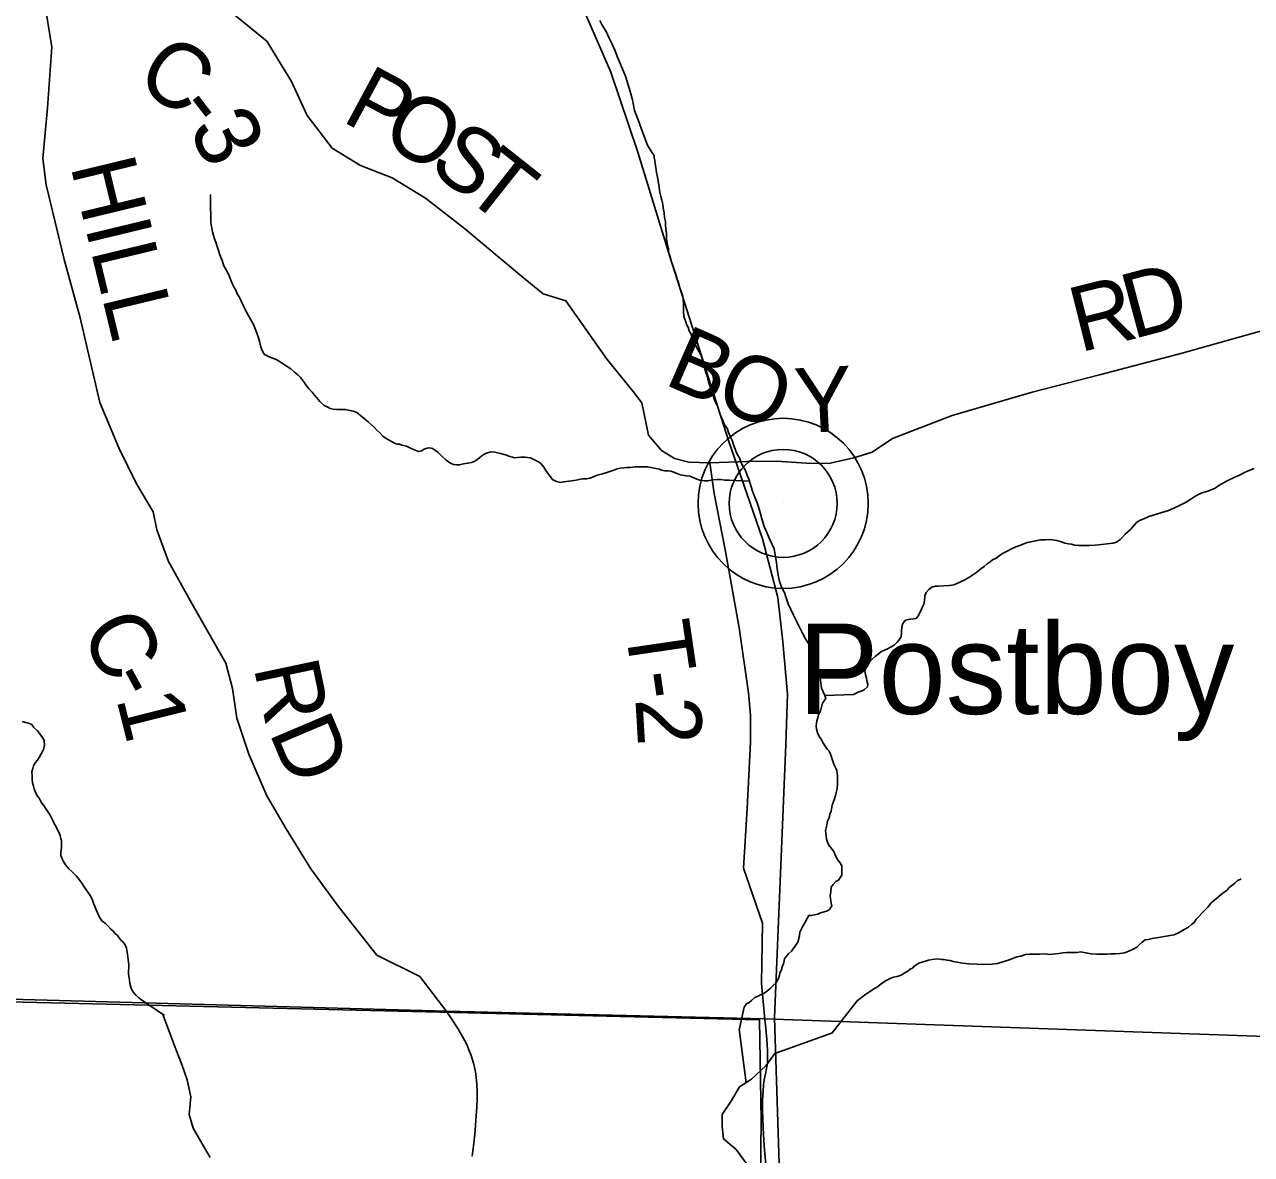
# Model space of a CAD drawing. Extents: x -14196 to 143, y -6096 to 28.
# Drawn here: x 58.549 to 59.622, y 18.723 to 19.711 of the extents above; entities that cross this region are included whole.
import ezdxf

# ---------------------------------------------------------------- set-up
doc = ezdxf.new("R2010")
doc.units = 0
for name, color, linetype in [('GM_X_Corporation', 7, 'Continuous'), ('GM_X_County_Road', 7, 'Continuous'), ('GM_X_County_Road_Text', 7, 'Continuous'), ('GM_X_Minor_River', 7, 'Continuous'), ('GM_X_Rail_Line', 7, 'Continuous'), ('GM_X_Township_Road', 7, 'Continuous'), ('GM_X_Township_Road_Text', 7, 'Continuous'), ('GM_X_Unincorporated', 7, 'Continuous'), ('GM_X_Unincorporated_Location', 7, 'Continuous'), ('GM_X_Unincorporated_Text', 7, 'Continuous')]:
    doc.layers.add(name, color=color, linetype=linetype)

msp = doc.modelspace()

# ---------------------------------------------------------------- linework, layer by layer
at = {"layer": 'GM_X_Corporation'}
for points in [[(58.1028, 23.6985), (58.1028, 18.8711), (58.9182, 18.8487), (59.1965, 18.8421), (59.6927, 18.8245), (59.855, 18.8221), (59.8722, 18.8218), (60.8954, 18.8061)], [(58.1028, 23.6985), (58.1028, 18.8711), (58.9182, 18.8487), (59.1965, 18.8421), (59.6927, 18.8245), (59.855, 18.8221), (59.8722, 18.8218), (60.8954, 18.8061)], [(60.8954, 18.8061), (59.8722, 18.8218), (59.855, 18.8221), (59.6927, 18.8245), (59.1965, 18.8421), (58.9182, 18.8487), (58.1028, 18.8711), (58.1028, 16.8985), (64.9028, 16.8985)], [(60.8954, 18.8061), (59.8722, 18.8218), (59.855, 18.8221), (59.6927, 18.8245), (59.1965, 18.8421), (58.9182, 18.8487), (58.1028, 18.8711), (58.1028, 16.8985), (62.3117, 16.8985)]]:
    msp.add_lwpolyline(points, dxfattribs=at)
msp.add_lwpolyline([(59.1921, 18.8411), (59.1934, 18.7532), (59.1927, 18.677), (59.1861, 17.9645), (58.1763, 17.99), (58.1952, 18.865)], close=True, dxfattribs=at)
at = {"layer": 'GM_X_County_Road'}
for points in [[(58.9184, 18.8482), (58.8948, 18.879), (58.8574, 18.8977), (58.8236, 18.9405), (58.7996, 18.9733), (58.7779, 19.0081), (58.7612, 19.037), (58.7454, 19.0734), (58.7348, 19.1051), (58.7311, 19.1308), (58.7252, 19.1531), (58.6954, 19.2052), (58.6751, 19.2419), (58.6649, 19.2698), (58.6618, 19.2853), (58.6468, 19.3104), (58.6316, 19.3415), (58.615, 19.381), (58.5979, 19.4551), (58.5837, 19.5061), (58.568, 19.5714), (58.5651, 19.5945), (58.5693, 19.6387), (58.5729, 19.6917), (58.5662, 19.7333)], [(58.7251, 19.726), (58.7612, 19.6969), (58.7826, 19.6617), (58.7963, 19.632), (58.8183, 19.6033), (58.8429, 19.5883), (58.8706, 19.5776), (58.8999, 19.5598), (58.934, 19.5333), (58.9856, 19.4901), (59.0027, 19.4761), (59.0226, 19.4698), (59.0588, 19.4186), (59.0815, 19.3907), (59.089, 19.3806), (59.095, 19.3523), (59.1064, 19.3389), (59.1176, 19.3319), (59.1302, 19.3288), (59.1484, 19.3282), (59.1815, 19.3294), (59.2069, 19.3297), (59.2332, 19.3281), (59.2525, 19.3278), (59.2744, 19.3325), (59.2906, 19.3375), (59.3082, 19.3494), (59.3605, 19.3697), (59.4306, 19.3901), (59.4895, 19.4053), (59.5604, 19.4238), (59.6011, 19.4351), (59.6362, 19.4451)], [(58.9406, 18.7221), (58.9416, 18.7288), (58.942, 18.733), (58.9427, 18.7385), (58.9432, 18.7447), (58.9443, 18.7576), (58.9448, 18.765), (58.9451, 18.7718), (58.945, 18.7786), (58.9448, 18.7847), (58.9446, 18.7878), (58.9442, 18.7908), (58.9438, 18.7939), (58.9433, 18.7968), (58.9426, 18.7999), (58.9417, 18.8034), (58.9398, 18.8099), (58.9379, 18.815), (58.936, 18.8195), (58.9326, 18.826), (58.9281, 18.8335), (58.9231, 18.8412), (58.9184, 18.8482)]]:
    msp.add_lwpolyline(points, dxfattribs=at)
at = {"layer": 'GM_X_Minor_River'}
for points in [[(59.0522, 19.7151), (59.0545, 19.7109), (59.058, 19.7053), (59.0604, 19.6996), (59.0631, 19.6943), (59.0654, 19.689), (59.0678, 19.6829), (59.0705, 19.6769), (59.0725, 19.672), (59.0748, 19.6663), (59.0768, 19.6598), (59.0788, 19.653)], [(59.0788, 19.653), (59.0808, 19.6458), (59.0828, 19.6364), (59.0863, 19.6273), (59.0898, 19.6167), (59.0941, 19.6061), (59.098, 19.5993), (59.1, 19.597), (59.1, 19.5951), (59.1004, 19.5925), (59.1008, 19.5898), (59.1012, 19.5864), (59.102, 19.5822), (59.1028, 19.578), (59.1037, 19.5731), (59.1041, 19.5689), (59.1049, 19.5648), (59.1057, 19.561), (59.1065, 19.5579), (59.1073, 19.5545), (59.1077, 19.5511), (59.1085, 19.5469), (59.109, 19.5428), (59.1098, 19.5393), (59.1098, 19.5363), (59.1102, 19.5325), (59.1106, 19.5287), (59.1107, 19.5242), (59.1111, 19.5204), (59.1119, 19.5173), (59.1123, 19.5154), (59.1124, 19.5124), (59.1135, 19.5094), (59.1143, 19.5063), (59.1151, 19.5037), (59.1163, 19.5007), (59.1183, 19.4946), (59.1191, 19.4923), (59.1199, 19.4889), (59.1214, 19.4851), (59.1222, 19.4813), (59.1238, 19.4772), (59.125, 19.4738), (59.1254, 19.4673), (59.1255, 19.4605), (59.1259, 19.4563), (59.1267, 19.454), (59.1275, 19.4514), (59.1283, 19.4487), (59.1295, 19.4468), (59.1306, 19.4438), (59.1318, 19.4412), (59.133, 19.4385), (59.1346, 19.4351), (59.1357, 19.4321), (59.1369, 19.4294), (59.1392, 19.4253), (59.1412, 19.4211), (59.1424, 19.4173), (59.1436, 19.4124), (59.1448, 19.4079), (59.1459, 19.4052), (59.1467, 19.4014), (59.1479, 19.3972), (59.1495, 19.3938), (59.1507, 19.3897), (59.1526, 19.3832), (59.1542, 19.3802), (59.1554, 19.3776), (59.1562, 19.3753), (59.157, 19.3723), (59.1581, 19.3692), (59.1593, 19.3666), (59.1605, 19.3636), (59.162, 19.3605), (59.1636, 19.3586), (59.1648, 19.3549), (59.1663, 19.3515), (59.1671, 19.3496), (59.1683, 19.3473), (59.1695, 19.3431), (59.1706, 19.3401), (59.1718, 19.3371), (59.1734, 19.3344), (59.1745, 19.3325), (59.1757, 19.3288), (59.1776, 19.325), (59.1796, 19.3216), (59.1812, 19.3174), (59.1827, 19.314), (59.1839, 19.3102), (59.1859, 19.3034), (59.1878, 19.2981), (59.1898, 19.2932), (59.191, 19.2898), (59.1926, 19.2849), (59.1941, 19.2792), (59.1961, 19.2727), (59.1985, 19.2674), (59.2008, 19.2618), (59.2032, 19.2568)], [(58.7118, 19.5628), (58.7118, 19.5625), (58.7119, 19.5575), (58.7119, 19.5533), (58.7119, 19.5503), (58.712, 19.5461), (58.712, 19.5427), (58.7121, 19.5389), (58.7125, 19.5362), (58.7129, 19.5336), (58.7137, 19.5302), (58.7145, 19.5271), (58.7153, 19.5241), (58.7165, 19.5211), (58.7176, 19.5173), (58.7188, 19.5139), (58.72, 19.5101), (58.722, 19.5052), (58.7235, 19.5006), (58.7259, 19.4965), (58.7278, 19.4927), (58.7294, 19.4889), (58.7309, 19.4851), (58.7325, 19.4817), (58.7341, 19.4791), (58.7352, 19.4761), (58.7368, 19.4734), (58.7383, 19.4704), (58.7403, 19.4659), (58.7426, 19.4613), (58.7446, 19.4579), (58.7496, 19.4485), (58.7508, 19.4454), (58.752, 19.4424), (58.7535, 19.4383), (58.7547, 19.4345), (58.7555, 19.4307), (58.7563, 19.428), (58.7575, 19.4254), (58.759, 19.4231), (58.7621, 19.4216), (58.7651, 19.4201), (58.7686, 19.419), (58.7713, 19.4175), (58.7739, 19.4157), (58.7781, 19.4131), (58.782, 19.4104), (58.7854, 19.4074), (58.7881, 19.4052), (58.7904, 19.4029), (58.7927, 19.4003), (58.7947, 19.3973), (58.7978, 19.3931), (58.8008, 19.3901), (58.8031, 19.3871), (58.8074, 19.3818), (58.8112, 19.3784), (58.8143, 19.377), (58.8166, 19.3758), (58.8192, 19.3751), (58.8223, 19.3748), (58.8261, 19.3748), (58.8299, 19.3748), (58.8337, 19.3741), (58.8367, 19.3734), (58.8398, 19.3723), (58.8429, 19.3697), (58.8463, 19.367), (58.8498, 19.364), (58.8524, 19.3618), (58.8551, 19.3595), (58.8574, 19.3569), (58.8601, 19.3543), (58.8624, 19.3516), (58.8655, 19.3494), (58.8732, 19.3453), (58.8751, 19.3445), (58.877, 19.3446), (58.8793, 19.3438), (58.8831, 19.3427), (58.8873, 19.3409), (58.8907, 19.3394), (58.8938, 19.3383), (58.8964, 19.3387), (58.8987, 19.3402), (58.9013, 19.341), (58.9036, 19.3414), (58.9059, 19.3407), (58.9078, 19.3396), (58.9109, 19.3373), (58.9139, 19.3343), (58.9178, 19.3306), (58.9216, 19.3279), (58.9243, 19.3268), (58.9269, 19.3265), (58.9296, 19.3265), (58.933, 19.3273), (58.9368, 19.3281), (58.9402, 19.3285), (58.9429, 19.3297), (58.9455, 19.3316)], [(58.9455, 19.3316), (58.9493, 19.3347), (58.953, 19.3366), (58.9572, 19.3378), (58.9606, 19.3375), (58.9656, 19.3364), (58.9698, 19.3353), (58.9736, 19.3338), (58.9759, 19.3331), (58.9778, 19.3327), (58.9804, 19.3328), (58.9831, 19.3332), (58.9869, 19.3332), (58.9892, 19.3328), (58.9918, 19.3325), (58.9987, 19.3291), (59.0006, 19.3276), (59.0033, 19.3246), (59.0052, 19.3216), (59.008, 19.3175), (59.011, 19.3137), (59.0145, 19.3118), (59.0179, 19.3111), (59.0209, 19.3115), (59.0255, 19.3123), (59.0316, 19.3132), (59.0369, 19.3144), (59.0407, 19.3144), (59.0437, 19.3148), (59.0467, 19.316), (59.0501, 19.3175), (59.0547, 19.3187), (59.0577, 19.3195), (59.0611, 19.3207), (59.0645, 19.3219), (59.0675, 19.323), (59.0702, 19.3235), (59.0732, 19.3239), (59.0759, 19.3243), (59.0793, 19.3243), (59.0831, 19.3247), (59.0873, 19.3248), (59.0903, 19.3248), (59.0941, 19.3248), (59.0971, 19.3241), (59.1013, 19.3234), (59.1044, 19.3227), (59.1063, 19.3219), (59.1093, 19.3212), (59.112, 19.3212), (59.1143, 19.3209), (59.1162, 19.3205), (59.123, 19.3179), (59.128, 19.3168), (59.131, 19.3165), (59.1345, 19.315), (59.1371, 19.3139), (59.1406, 19.3128), (59.144, 19.3125), (59.147, 19.3125), (59.1508, 19.3133), (59.155, 19.3137), (59.158, 19.3137), (59.1618, 19.313), (59.1637, 19.313), (59.1656, 19.3131), (59.1832, 19.3123)], [(59.5545, 19.2887), (59.5594, 19.291), (59.5647, 19.2937), (59.5692, 19.2965), (59.5737, 19.2995), (59.579, 19.3019), (59.5832, 19.3031), (59.587, 19.3046), (59.5904, 19.3062), (59.5938, 19.3085), (59.5979, 19.3108), (59.6021, 19.3131), (59.607, 19.3155), (59.6119, 19.3174), (59.6157, 19.3194), (59.6194, 19.3213), (59.6247, 19.3233)], [(59.2492, 19.1247), (59.2742, 19.1257), (59.2784, 19.1277), (59.2818, 19.1289), (59.2837, 19.13), (59.2863, 19.1323), (59.2867, 19.1346), (59.2859, 19.1376), (59.2855, 19.1399), (59.2847, 19.143), (59.2842, 19.1464), (59.2853, 19.1498), (59.2868, 19.1517), (59.2883, 19.154), (59.2906, 19.1567), (59.2932, 19.159), (59.2988, 19.1632), (59.3038, 19.1656), (59.3072, 19.1675), (59.3098, 19.1687), (59.3124, 19.1714), (59.3139, 19.1733), (59.3158, 19.176), (59.3161, 19.1798), (59.3161, 19.1817), (59.3165, 19.1836), (59.3168, 19.1862), (59.3179, 19.1885), (59.3198, 19.1908), (59.3221, 19.1912), (59.3243, 19.1916), (59.327, 19.1917), (59.3289, 19.1921), (59.3311, 19.1947), (59.3322, 19.1974), (59.3334, 19.1993), (59.3341, 19.2012), (59.3356, 19.2047), (59.3363, 19.2077), (59.3366, 19.2119), (59.3377, 19.215), (59.34, 19.2176), (59.3426, 19.2196), (59.3456, 19.2204), (59.3483, 19.2204), (59.3578, 19.2209), (59.3601, 19.2213), (59.362, 19.2217), (59.3639, 19.2225), (59.3673, 19.224), (59.371, 19.2256), (59.3756, 19.2283), (59.3786, 19.2302), (59.3812, 19.2321), (59.3835, 19.2337), (59.3857, 19.2356), (59.3884, 19.2375), (59.391, 19.2398), (59.3936, 19.2418), (59.3959, 19.2433), (59.3989, 19.2449), (59.4015, 19.2468), (59.4046, 19.2491), (59.4091, 19.2514), (59.4129, 19.2534), (59.4163, 19.2549), (59.4197, 19.2561), (59.4231, 19.2573), (59.4261, 19.2585), (59.4295, 19.2593), (59.4333, 19.2601), (59.4378, 19.2609), (59.442, 19.2609), (59.4466, 19.2613), (59.4519, 19.2603), (59.4561, 19.2592), (59.4591, 19.258), (59.4622, 19.2573), (59.4649, 19.257), (59.4679, 19.2562), (59.4713, 19.2559), (59.4755, 19.2559), (59.4804, 19.256), (59.4857, 19.2564), (59.4911, 19.2569), (59.496, 19.2573), (59.5013, 19.2581), (59.5043, 19.2589), (59.5073, 19.2612), (59.5092, 19.2631), (59.5118, 19.2658), (59.5141, 19.2678), (59.5164, 19.2701), (59.5216, 19.2762), (59.5242, 19.2777), (59.528, 19.2793), (59.5325, 19.2812), (59.5382, 19.2832), (59.5439, 19.2848), (59.5496, 19.2867), (59.5545, 19.2887)], [(59.2032, 19.2568), (59.2047, 19.2531), (59.2063, 19.2443), (59.2068, 19.2413), (59.2072, 19.2379), (59.2076, 19.2337), (59.2084, 19.2299), (59.2096, 19.2246), (59.2112, 19.2197), (59.2127, 19.2167), (59.2139, 19.2148), (59.2151, 19.211), (59.2171, 19.2049), (59.2194, 19.2), (59.2217, 19.1951), (59.2245, 19.1891), (59.2276, 19.1834), (59.2299, 19.1788), (59.2322, 19.1743), (59.235, 19.1698), (59.2373, 19.166), (59.2388, 19.1641), (59.2404, 19.16), (59.2412, 19.1569), (59.242, 19.1539), (59.2428, 19.1516), (59.2436, 19.1482), (59.2444, 19.1459), (59.2448, 19.1429), (59.2461, 19.1311), (59.2492, 19.1247), (59.25, 19.1224), (59.2485, 19.1201), (59.247, 19.1182), (59.2452, 19.111), (59.2437, 19.1083), (59.2429, 19.1053), (59.2422, 19.1026), (59.2415, 19.0984), (59.2419, 19.0954), (59.2427, 19.0923), (59.2443, 19.0889), (59.2458, 19.0867), (59.2474, 19.0837), (59.2493, 19.0806), (59.2512, 19.078), (59.2528, 19.0761), (59.254, 19.0735), (59.2551, 19.0708), (59.2559, 19.0682), (59.2571, 19.0648), (59.2587, 19.0614), (59.2595, 19.0591), (59.2599, 19.0568), (59.2603, 19.0542), (59.2603, 19.0511), (59.2603, 19.0477), (59.26, 19.0435), (59.2593, 19.0412), (59.2586, 19.0374), (59.2575, 19.0344), (59.2564, 19.0313), (59.2556, 19.029), (59.2553, 19.0271), (59.2546, 19.0237), (59.2535, 19.021), (59.2531, 19.0191), (59.2527, 19.0172), (59.2516, 19.0149), (59.2509, 19.0115), (59.2502, 19.0092), (59.2498, 19.0069), (59.2499, 19.0043), (59.2507, 18.9993), (59.2515, 18.9967), (59.2526, 18.994), (59.2569, 18.9884), (59.258, 18.9861), (59.26, 18.9816), (59.2627, 18.9782), (59.2639, 18.9755), (59.264, 18.9676), (59.261, 18.9633), (59.2587, 18.9622), (59.2565, 18.9595), (59.2546, 18.9572), (59.2543, 18.9534), (59.2539, 18.9496), (59.254, 18.9473), (59.2544, 18.9454), (59.2548, 18.9431), (59.2552, 18.9409), (59.2533, 18.9378), (59.2514, 18.9366), (59.2484, 18.9355), (59.2454, 18.9347), (59.2431, 18.9335), (59.2401, 18.9331), (59.237, 18.9323), (59.2351, 18.9323), (59.234, 18.9304)], [(58.5471, 19.102), (58.5502, 19.1013), (58.5525, 19.1005), (58.5555, 19.0994), (58.5574, 19.0968), (58.5605, 19.0938), (58.5632, 19.0904), (58.5651, 19.0878), (58.5663, 19.0851), (58.5667, 19.0813), (58.5657, 19.0775), (58.5638, 19.0737), (58.5619, 19.0706), (58.5604, 19.0683), (58.5586, 19.066), (58.5571, 19.0633), (58.5564, 19.0611), (58.5556, 19.058), (58.5557, 19.0546), (58.5557, 19.0515)], [(58.5557, 19.0515), (58.5561, 19.0485), (58.5569, 19.0455), (58.5577, 19.0432), (58.5585, 19.0409), (58.5601, 19.0372), (58.562, 19.0349), (58.5631, 19.0326), (58.5643, 19.0307), (58.5659, 19.0285), (58.5674, 19.0262), (58.5717, 19.0202), (58.5724, 19.0183), (58.5736, 19.016), (58.5748, 19.0134), (58.5767, 19.01), (58.5779, 19.0073), (58.5794, 19.0047), (58.5802, 19.002), (58.581, 18.9998), (58.5814, 18.9979), (58.5815, 18.9948), (58.5815, 18.9922), (58.5808, 18.9872), (58.5808, 18.9849), (58.582, 18.9819), (58.5832, 18.9796), (58.5851, 18.9766), (58.5878, 18.9732), (58.5905, 18.971), (58.5924, 18.9691), (58.5943, 18.9672), (58.5962, 18.965), (58.5993, 18.9608), (58.602, 18.9567), (58.6044, 18.9529), (58.6067, 18.9499), (58.6078, 18.948), (58.6086, 18.9457), (58.6094, 18.9431), (58.6106, 18.9404), (58.6118, 18.9374), (58.6129, 18.9347), (58.6145, 18.9317), (58.6168, 18.9279), (58.6199, 18.9253), (58.6222, 18.9231), (58.6245, 18.9204), (58.6264, 18.9189), (58.628, 18.917), (58.6306, 18.9148), (58.6334, 18.911), (58.6353, 18.9091), (58.6368, 18.9073), (58.6384, 18.9039), (58.6392, 18.8985), (58.6404, 18.8894), (58.6402, 18.8811), (58.6406, 18.8777), (58.641, 18.8758), (58.6414, 18.8731), (58.6422, 18.8697), (58.643, 18.8674), (58.6445, 18.8652), (58.6465, 18.8629), (58.6492, 18.8603), (58.6515, 18.8588), (58.6515, 18.8588), (58.6715, 18.8449)], [(59.2554, 18.8297), (59.2774, 18.8579), (59.2812, 18.8606), (59.285, 18.8637), (59.2891, 18.8664), (59.2921, 18.8683), (59.2951, 18.8702), (59.297, 18.8714), (59.3004, 18.8741), (59.3027, 18.8756), (59.3046, 18.8764), (59.3064, 18.8772), (59.3091, 18.8784), (59.3125, 18.8792), (59.3159, 18.8803), (59.3185, 18.8819), (59.3216, 18.8838), (59.3238, 18.8854), (59.3257, 18.8865), (59.3276, 18.8884), (59.3295, 18.8896), (59.3314, 18.8908), (59.3397, 18.8935), (59.3431, 18.8939), (59.348, 18.8944), (59.3511, 18.894), (59.3533, 18.894), (59.356, 18.8933), (59.3587, 18.893), (59.3613, 18.8922), (59.3648, 18.8915), (59.3693, 18.8908), (59.375, 18.8901), (59.3823, 18.8898), (59.3883, 18.8895), (59.3956, 18.8899), (59.4001, 18.8904), (59.4039, 18.8915), (59.4077, 18.8927), (59.4111, 18.8939), (59.4141, 18.8951), (59.4171, 18.8962), (59.4205, 18.897), (59.4247, 18.8982), (59.4285, 18.8986), (59.4327, 18.8987), (59.4369, 18.8987), (59.4425, 18.8988), (59.4452, 18.8984), (59.4482, 18.8985), (59.4509, 18.8989), (59.4539, 18.8993), (59.4574, 18.8997), (59.4608, 18.9001), (59.4638, 18.9001), (59.4665, 18.9002), (59.4699, 18.9002), (59.4729, 18.9006), (59.4775, 18.8999), (59.482, 18.8988), (59.487, 18.8985), (59.4912, 18.8985), (59.4938, 18.8986), (59.4961, 18.8986), (59.4991, 18.899), (59.5029, 18.899), (59.5071, 18.8991), (59.5113, 18.8999), (59.5151, 18.9011), (59.5188, 18.903), (59.5219, 18.9046), (59.5237, 18.9065), (59.5267, 18.9092), (59.5294, 18.9111), (59.532, 18.9115), (59.5354, 18.9123), (59.5411, 18.9131), (59.5476, 18.9143), (59.5548, 18.9156), (59.5589, 18.9175), (59.5635, 18.9202), (59.5672, 18.9221), (59.5699, 18.9245), (59.5721, 18.9264), (59.574, 18.9291), (59.5762, 18.9317), (59.5789, 18.9344), (59.5815, 18.9371), (59.5841, 18.9398), (59.5871, 18.9436), (59.592, 18.9475), (59.5958, 18.9509), (59.5984, 18.9529), (59.6006, 18.9544), (59.6025, 18.9567), (59.6052, 18.9586), (59.6078, 18.9606), (59.61, 18.9629)], [(59.61, 18.9629), (59.6123, 18.964), (59.6134, 18.9644)], [(59.234, 18.9304), (59.2318, 18.9266), (59.2299, 18.9231), (59.2288, 18.9208), (59.2273, 18.9178), (59.227, 18.9147), (59.2255, 18.909), (59.2229, 18.9052), (59.2199, 18.9013), (59.2173, 18.899), (59.2158, 18.8971), (59.2139, 18.8948), (59.2136, 18.8929), (59.2129, 18.8903), (59.2117, 18.8876), (59.211, 18.8842), (59.2099, 18.8822), (59.2096, 18.8803), (59.2085, 18.8773), (59.2066, 18.8738), (59.2043, 18.8715), (59.2013, 18.8685), (59.1991, 18.8665), (59.1961, 18.8646), (59.193, 18.8631), (59.1908, 18.8619), (59.1878, 18.8607), (59.1851, 18.858), (59.1829, 18.8565), (59.1806, 18.8553), (59.1787, 18.8523), (59.1742, 18.8326)], [(58.7115, 18.7209), (58.7035, 18.7348), (58.6966, 18.7466), (58.6931, 18.7583), (58.6945, 18.7738), (58.6913, 18.7886), (58.6866, 18.8022), (58.6816, 18.8155), (58.6701, 18.8459)], [(59.1802, 18.7862), (59.1743, 18.8329)], [(59.2054, 18.8119), (59.2558, 18.8297)], [(59.1804, 18.7158), (59.1716, 18.7278), (59.1606, 18.7372), (59.1593, 18.7479), (59.1593, 18.7585), (59.1675, 18.7707), (59.1746, 18.7825), (59.1851, 18.7894), (59.1975, 18.8009), (59.2054, 18.8119)]]:
    msp.add_lwpolyline(points, dxfattribs=at)
at = {"layer": 'GM_X_Rail_Line'}
for points in [[(59.2051, 18.843), (59.2149, 19.0819), (59.2165, 19.1261), (59.2125, 19.1718), (59.2079, 19.2105), (59.1947, 19.2618), (59.165, 19.3479), (59.1135, 19.5088), (59.0855, 19.5998), (59.0619, 19.6698), (59.0358, 19.7301)], [(59.2051, 18.843), (59.2136, 18.5784), (59.229, 18.4834), (59.2448, 18.4139), (59.2533, 18.3634), (59.252, 18.317), (59.2363, 18.2523), (59.1968, 18.0919), (59.0934, 17.6358), (59.0658, 17.5504), (59.0253, 17.4639), (58.9705, 17.3468), (58.7784, 16.9546), (58.7533, 16.8985)]]:
    msp.add_lwpolyline(points, dxfattribs=at)
at = {"layer": 'GM_X_Township_Road'}
for points in [[(59.1967, 18.8415), (59.1937, 18.873), (59.1946, 18.9256), (59.1779, 18.9739), (59.1812, 19.0261), (59.1842, 19.0839), (59.184, 19.1075), (59.1824, 19.1272), (59.1741, 19.184), (59.1622, 19.2506), (59.1522, 19.3013), (59.1484, 19.3282)], [(59.1984, 18.7053), (59.1961, 18.7306), (59.1951, 18.7467), (59.1945, 18.7622), (59.1946, 18.7709), (59.1951, 18.7789), (59.1956, 18.7843), (59.1962, 18.7887), (59.1973, 18.7941), (59.1981, 18.7987), (59.1986, 18.8015), (59.1989, 18.8045), (59.1991, 18.8078), (59.1991, 18.8147), (59.1985, 18.8244), (59.1973, 18.8366), (59.1967, 18.8415)]]:
    msp.add_lwpolyline(points, dxfattribs=at)
at = {"layer": 'GM_X_Unincorporated'}
for radius in [0.0744, 0.0472]:
    msp.add_circle((59.2127, 19.2928), radius, dxfattribs=at)
at = {"layer": 'GM_X_Unincorporated_Location'}
msp.add_line((59.2127, 19.2928), (59.2127, 19.2928), dxfattribs=at)

# ---------------------------------------------------------------- texts
at = {"layer": 'GM_X_County_Road_Text'}
for s, height, rotation, p in [('C', 0.0568, 326.0047, (58.6442, 19.6595)), ('P', 0.0568, 331.6922, (58.8254, 19.6276)), ('-', 0.0568, 307.6052, (58.6794, 19.6367)), ('O', 0.0568, 329.9171, (58.8588, 19.6097)), ('3', 0.0568, 296.3859, (58.6921, 19.6207)), ('S', 0.0568, 323.705, (58.9007, 19.5855)), ('T', 0.0568, 321.636, (58.9311, 19.5631)), ('HILL', 0.05682, 283.5704, (58.5891, 19.5882)), ('D', 0.0568, 14.9067, (59.5181, 19.4362)), ('R', 0.0568, 14.0504, (59.4719, 19.4246)), ('B', 0.0568, 336.3284, (59.1072, 19.3976)), ('O', 0.0568, 336.7838, (59.1504, 19.3786)), ('Y', 0.0568, 2.8998, (59.2239, 19.354)), ('C', 0.0568, 299.0042, (58.5969, 19.18)), ('R', 0.0568, 281.9154, (58.7494, 19.1499)), ('-', 0.0568, 298.4329, (58.6194, 19.1393)), ('1', 0.0568, 284.083, (58.6292, 19.1223)), ('D', 0.0568, 292.9988, (58.7626, 19.093))]:
    msp.add_text(s, height=height, rotation=rotation, dxfattribs=at).set_placement(p)
at = {"layer": 'GM_X_Township_Road_Text'}
for s, rotation, p in [('T', 278.3913, (59.074, 19.1858)), ('-', 278.161, (59.0802, 19.1438)), ('2', 273.3741, (59.0834, 19.122))]:
    msp.add_text(s, height=0.0568, rotation=rotation, dxfattribs=at).set_placement(p)
at = {"layer": 'GM_X_Unincorporated_Text'}
msp.add_text('Postboy', height=0.07898, rotation=0, dxfattribs=at).set_placement((59.2257, 19.1087))

doc.saveas('drawing.dxf')
